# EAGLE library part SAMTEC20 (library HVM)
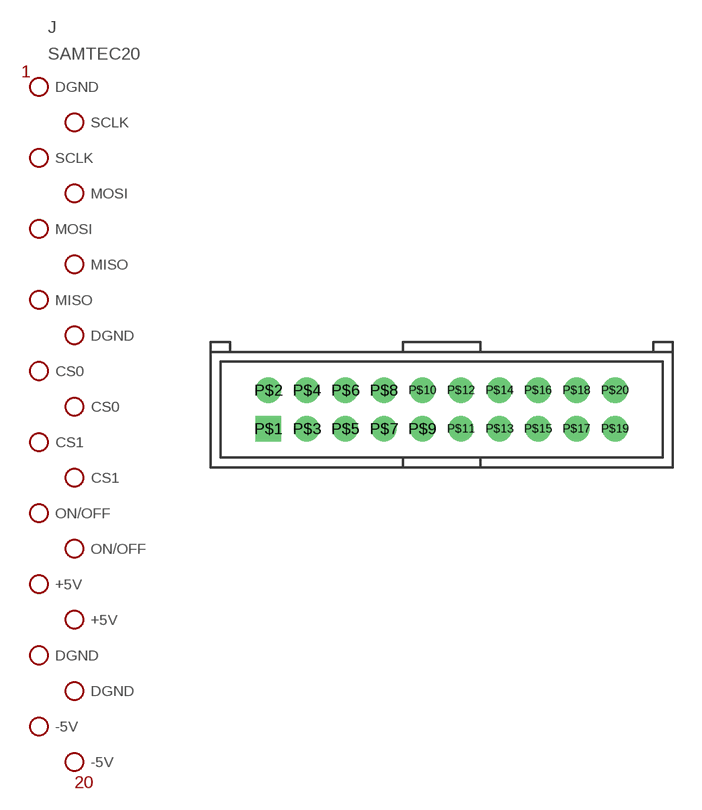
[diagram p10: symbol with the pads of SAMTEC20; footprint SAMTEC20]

Designator prefix J

## SAMTEC20  [SAMTEC20]
P$1  DGND  pas
P$2  SCLK  pas
P$3  SCLK  pas
P$4  MOSI  pas
P$5  MOSI  pas
P$6  MISO  pas
P$7  MISO  pas
P$8  DGND  pas
P$9  CS0  pas
P$10  CS0  pas
P$11  CS1  pas
P$12  CS1  pas
P$13  ON/OFF  pas
P$14  ON/OFF  pas
P$15  +5V  pas
P$16  +5V  pas
P$17  DGND  pas
P$18  DGND  pas
P$19  -5V  pas
P$20  -5V  pas

## Footprint SAMTEC20 (pad centres in mm)
drill 0.813 square: P$1 -9,-1
drill 0.813 round: P$2 -9,1; P$3 -7,-1; P$4 -7,1; P$5 -5,-1; P$6 -5,1; P$7 -3,-1; P$8 -3,1; P$9 -1,-1; P$10 -1,1; P$11 1,-1; P$12 1,1; P$13 3,-1; P$14 3,1; P$15 5,-1; P$16 5,1; P$17 7,-1; P$18 7,1; P$19 9,-1; P$20 9,1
